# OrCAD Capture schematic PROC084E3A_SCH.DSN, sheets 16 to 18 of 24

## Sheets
16 12. PRG1 GB_ETHERNET RGMII 2: size C; title: PRG1 GB_ETHERNET RGMII 2
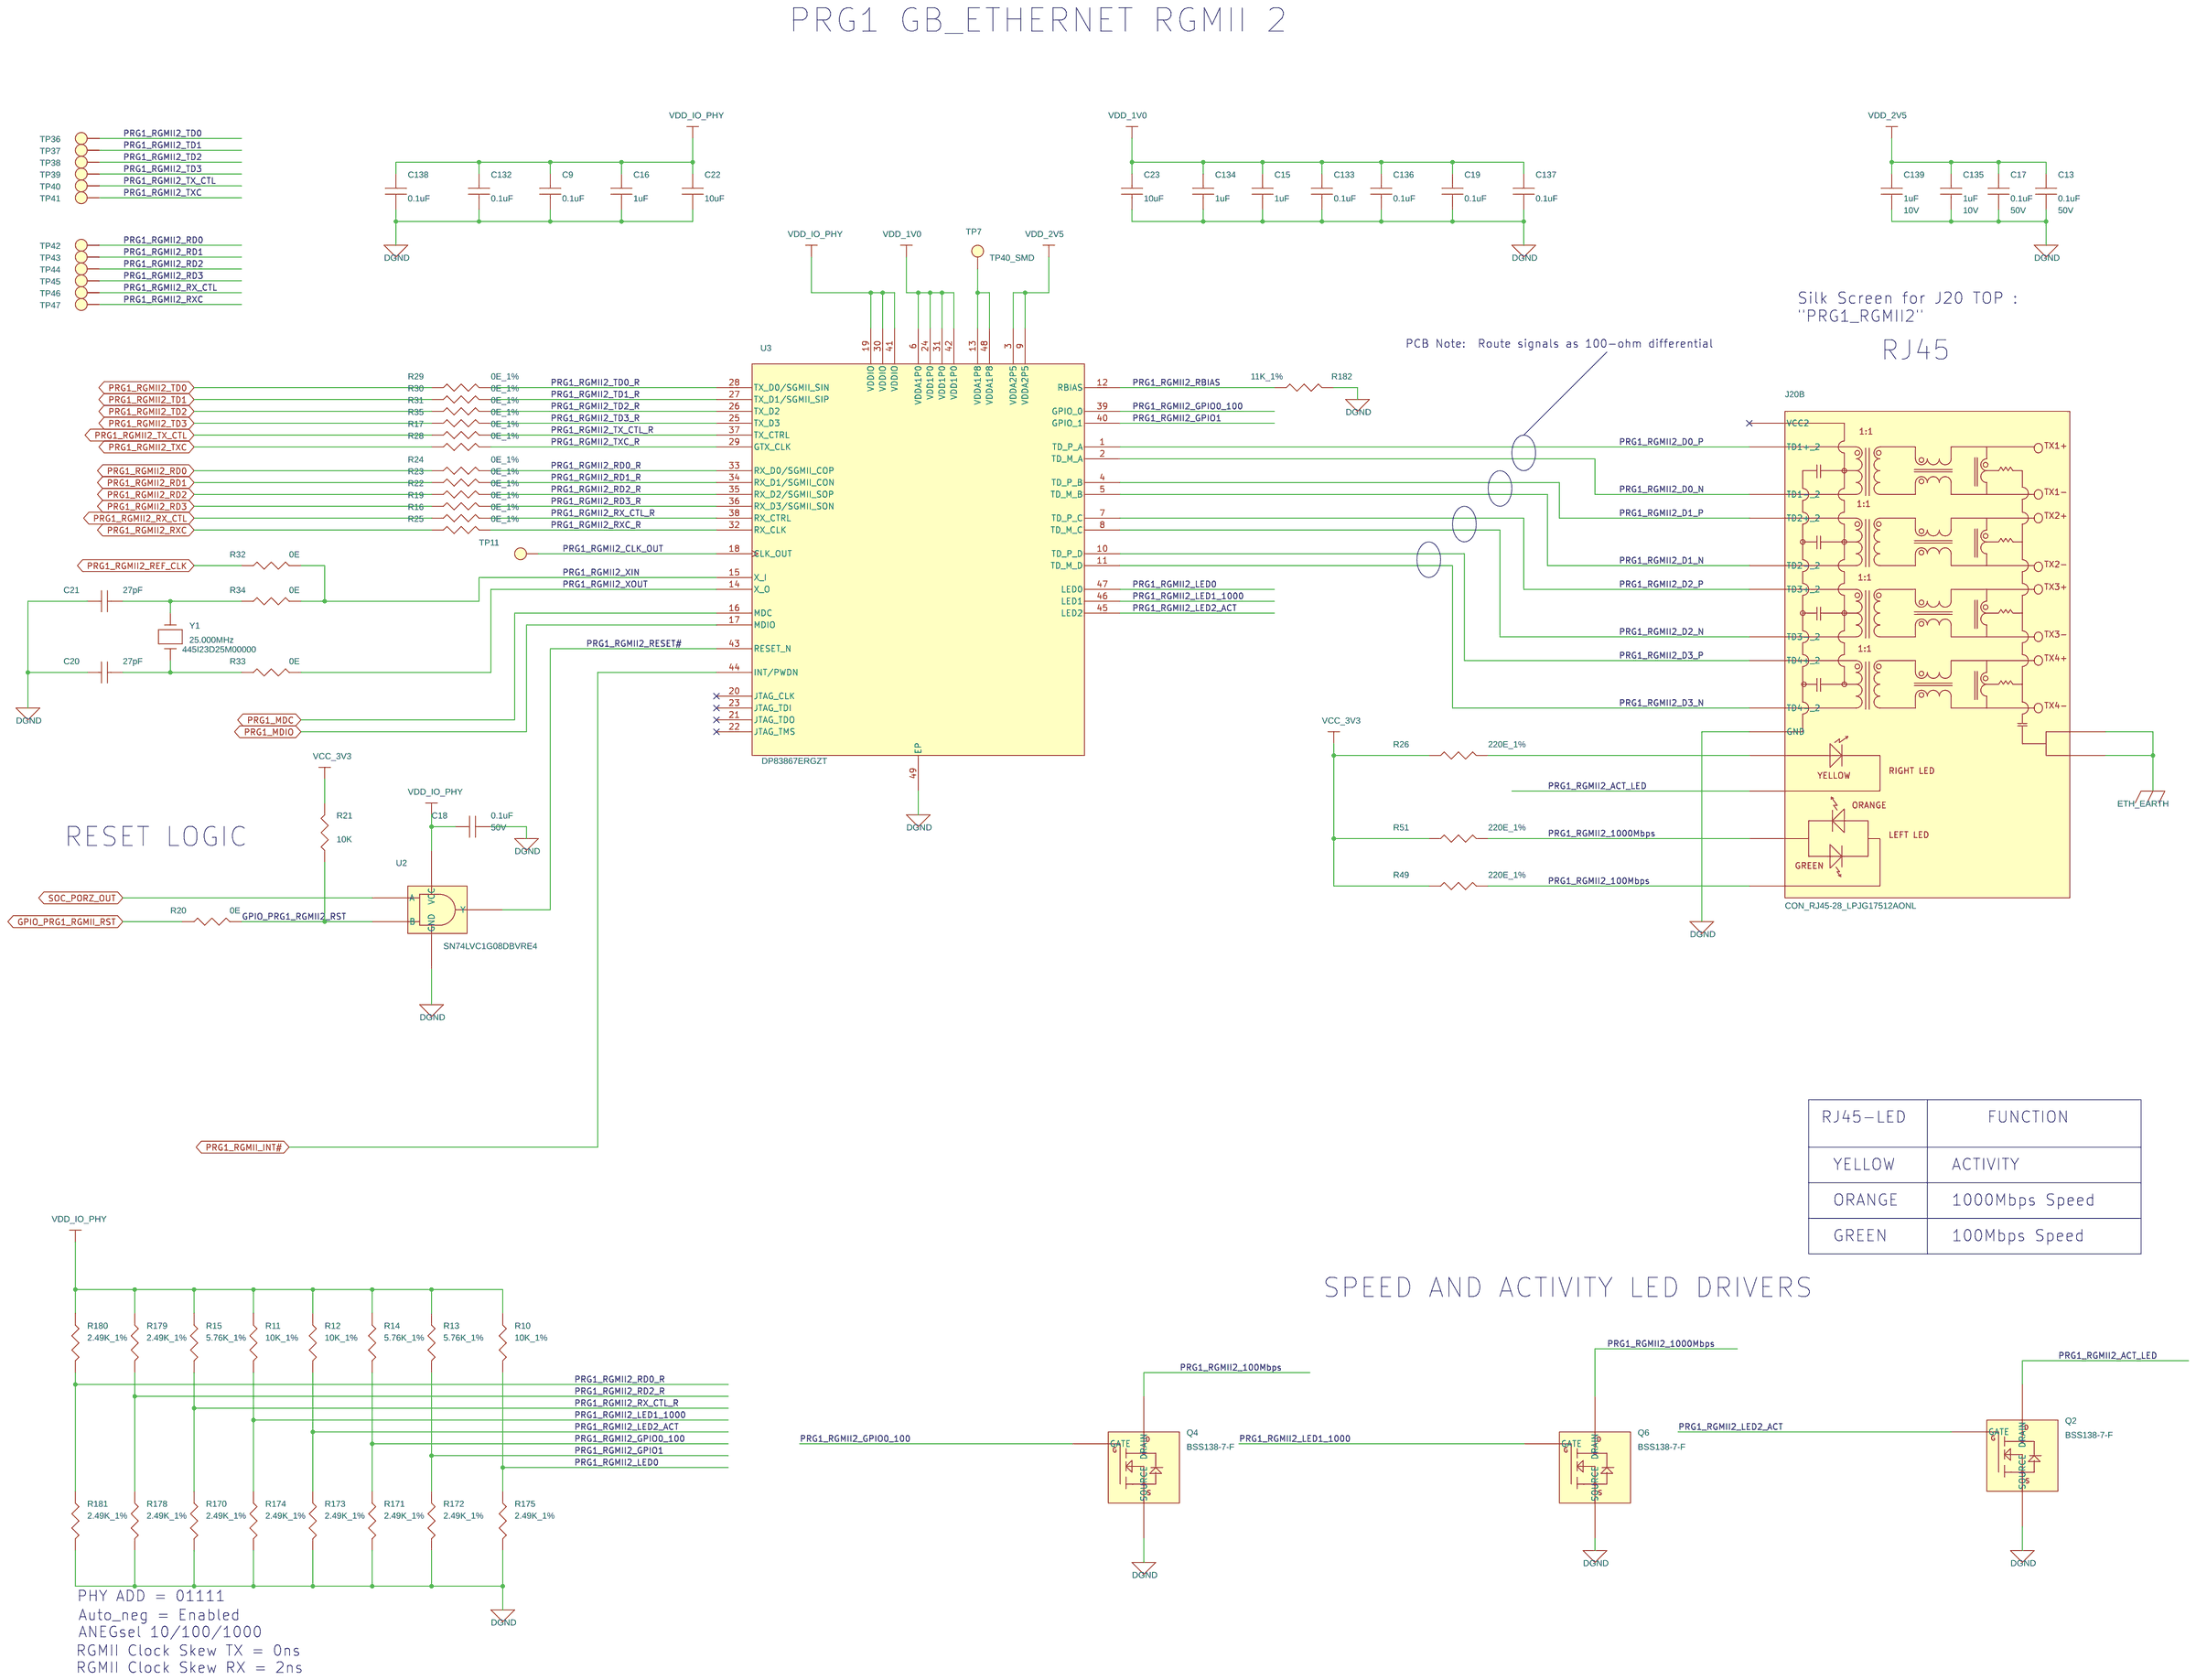
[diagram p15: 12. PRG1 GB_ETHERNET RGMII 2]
17 13. CAN TRANSCEIVERS - 01: size C; title: CAN TRANSCEIVERS - 01
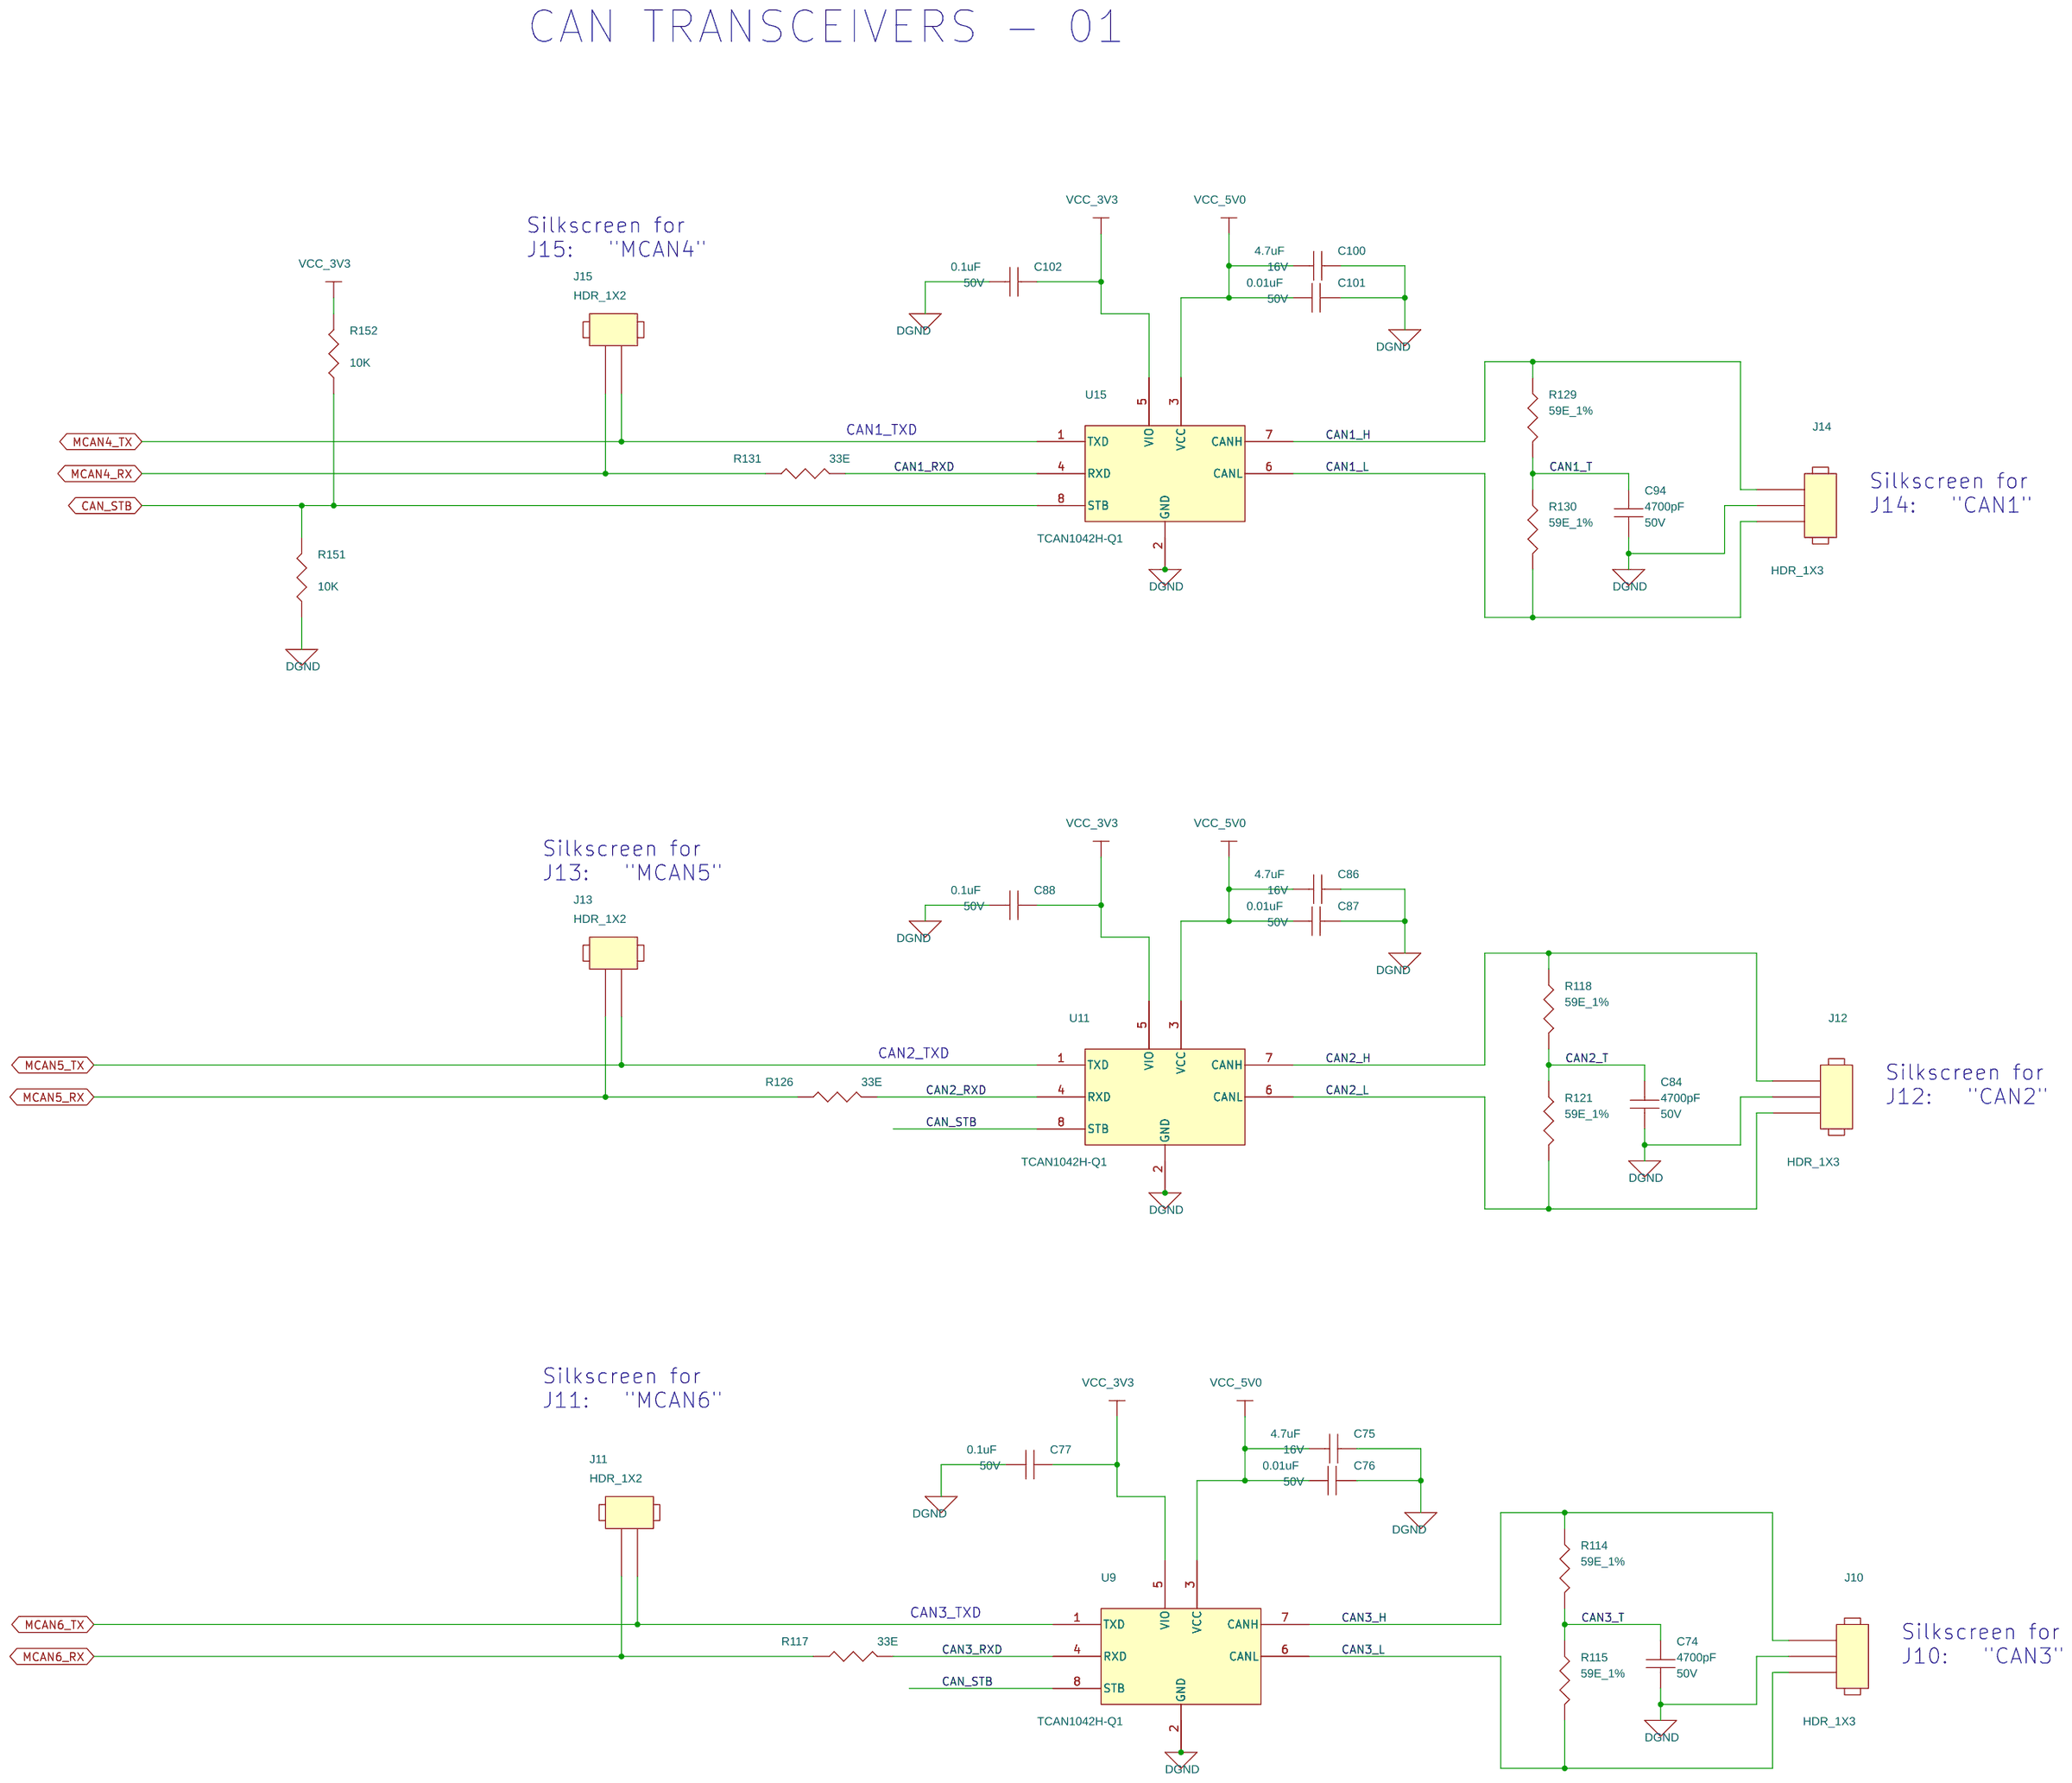
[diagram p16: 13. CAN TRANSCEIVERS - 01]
18 14. CAN TRANSCEIVERS - 02: size C; title: CAN TRANSCEIVERS - 02
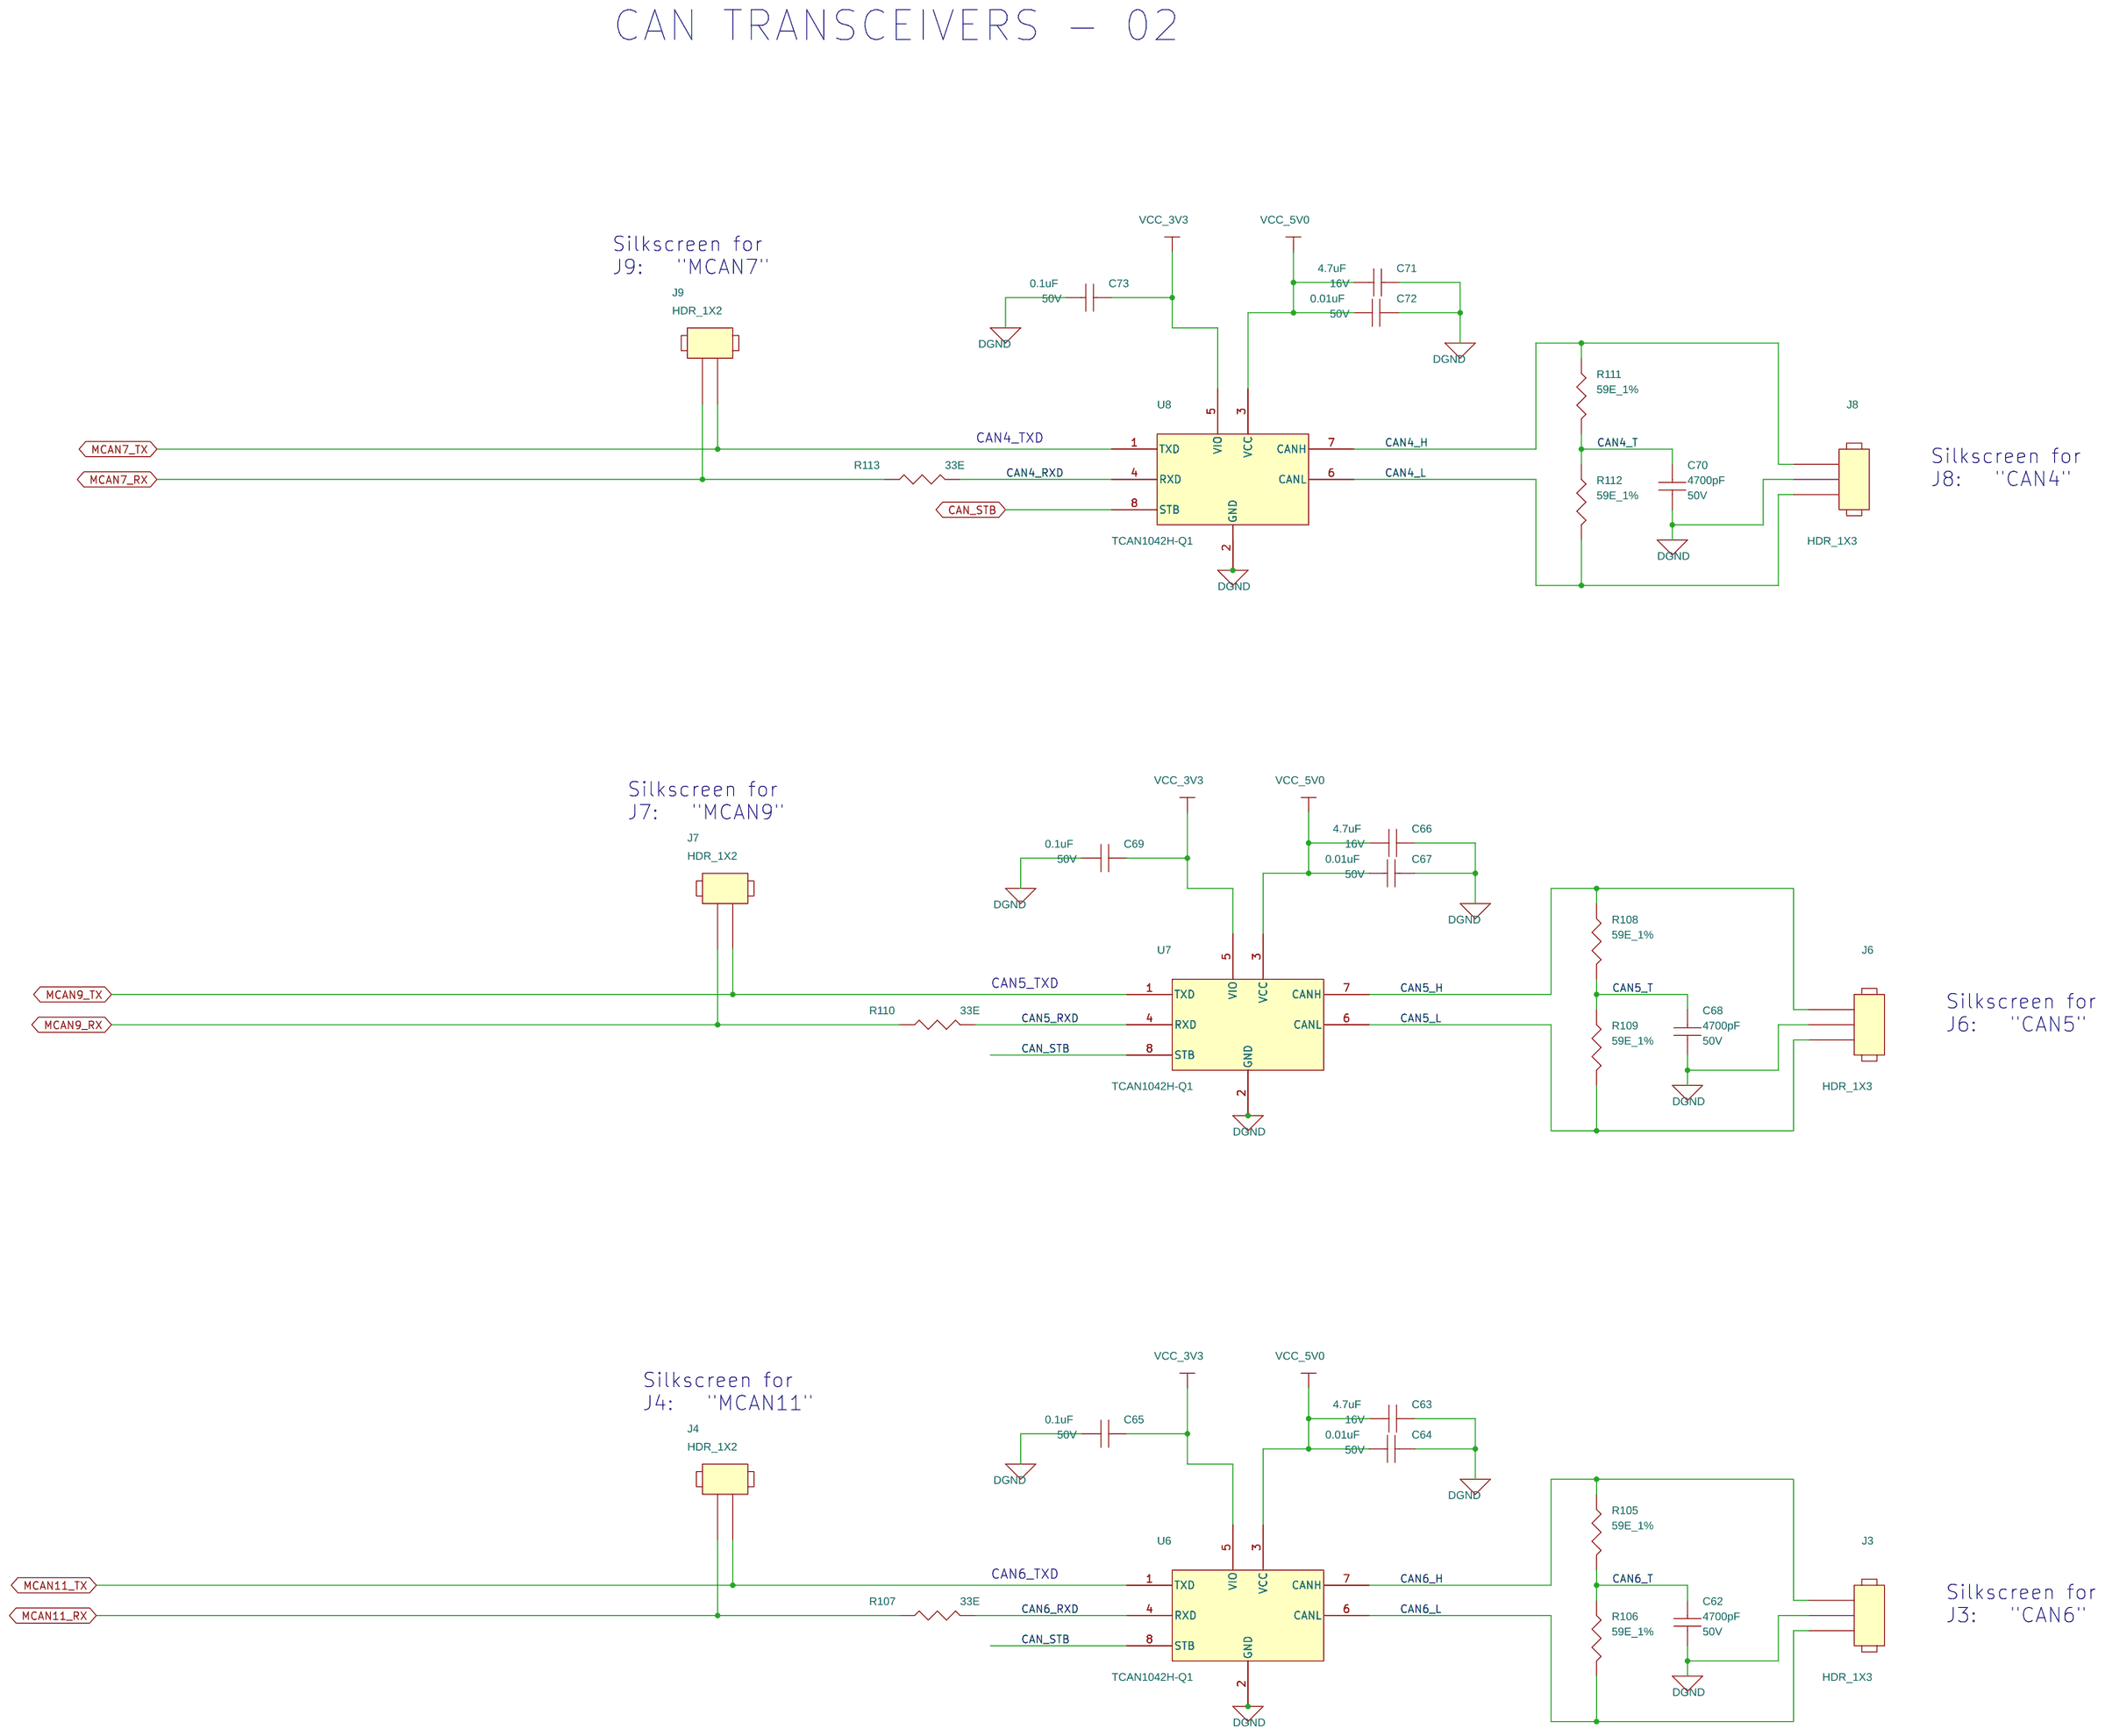
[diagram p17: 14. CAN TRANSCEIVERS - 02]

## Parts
sheet 12. PRG1 GB_ETHERNET RGMII 2
C9  0.1uF  [CAP0402_0-75]
C13  0.1uF  [CAP0402_0-75]
C15  1uF  [CAP0402_0-75]
C16  1uF  [CAP0402_0-75]
C17  0.1uF  [CAP0402_0-75]
C18  0.1uF  [CAP0402_0-75]
C19  0.1uF  [CAP0402_0-75]
C20  27pF  [CAP0402_0-75]
C21  27pF  [CAP0402_0-75]
C22  10uF  [CAP0805_1-5]
C23  10uF  [CAP0805_1-5]
C132  0.1uF  [CAP0402_0-75]
C133  0.1uF  [CAP0402_0-75]
C134  1uF  [CAP0402_0-75]
C135  1uF  [CAP0402_0-75]
C136  0.1uF  [CAP0402_0-75]
C137  0.1uF  [CAP0402_0-75]
C138  0.1uF  [CAP0402_0-75]
C139  1uF  [CAP0402_0-75]
J20  CON_RJ45-28_LPJG17512AONL  [CON_RJ45-28_LPJG17512_S_R_T_25-3]  (sections A,B)
Q2  BSS138-7-F  [SOT23-123_1-1]
Q4  BSS138-7-F  [SOT23-123_1-1]
Q6  BSS138-7-F  [SOT23-123_1-1]
R10  10K_1%  [RES0402_0-5]
R11  10K_1%  [RES0402_0-5]
R12  10K_1%  [RES0402_0-5]
R13  5.76K_1%  [RES0402_0-5]
R14  5.76K_1%  [RES0402_0-5]
R15  5.76K_1%  [RES0402_0-5]
R16  0E_1%  [RES0402_0-5]
R17  0E_1%  [RES0402_0-5]
R19  0E_1%  [RES0402_0-5]
R20  0E  [RES0402_0-5]
R21  10K  [RES0402_0-5]
R22  0E_1%  [RES0402_0-5]
R23  0E_1%  [RES0402_0-5]
R24  0E_1%  [RES0402_0-5]
R25  0E_1%  [RES0402_0-5]
R26  220E_1%  [RES0402_0-5]
R28  0E_1%  [RES0402_0-5]
R29  0E_1%  [RES0402_0-5]
R30  0E_1%  [RES0402_0-5]
R31  0E_1%  [RES0402_0-5]
R32  0E  [RES0402_0-5]
R33  0E  [RES0402_0-5]
R34  0E  [RES0402_0-5]
R35  0E_1%  [RES0402_0-5]
R49  220E_1%  [RES0402_0-5]
R51  220E_1%  [RES0402_0-5]
R170  2.49K_1%  [RES0402_0-5]
R171  2.49K_1%  [RES0402_0-5]
R172  2.49K_1%  [RES0402_0-5]
R173  2.49K_1%  [RES0402_0-5]
R174  2.49K_1%  [RES0402_0-5]
R175  2.49K_1%  [RES0402_0-5]
R178  2.49K_1%  [RES0402_0-5]
R179  2.49K_1%  [RES0402_0-5]
R180  2.49K_1%  [RES0402_0-5]
R181  2.49K_1%  [RES0402_0-5]
R182  11K_1%  [RES0402_0-5]
TP7  TP40_SMD  [TP40_SMD]
TP11  TP40_SMD  [TP40_SMD]
TP36  TP20_SMD  [TP20_SMD]
TP37  TP20_SMD  [TP20_SMD]
TP38  TP20_SMD  [TP20_SMD]
TP39  TP20_SMD  [TP20_SMD]
TP40  TP20_SMD  [TP20_SMD]
TP41  TP20_SMD  [TP20_SMD]
TP42  TP20_SMD  [TP20_SMD]
TP43  TP20_SMD  [TP20_SMD]
TP44  TP20_SMD  [TP20_SMD]
TP45  TP20_SMD  [TP20_SMD]
TP46  TP20_SMD  [TP20_SMD]
TP47  TP20_SMD  [TP20_SMD]
U2  SN74LVC1G08DBVRE4  [SOT23-5]
U3  DP83867ERGZT  [VQFN48_19-68_285X285]
Y1  25.000MHz  [XTAL_ABM3_205X130_SMD_1-4]
sheet 13. CAN TRANSCEIVERS - 01
C74  4700pF  [CAP0402_0-75]
C75  4.7uF  [CAP0603_1]
C76  0.01uF  [CAP0402_0-75]
C77  0.1uF  [CAP0402_0-75]
C84  4700pF  [CAP0402_0-75]
C86  4.7uF  [CAP0603_1]
C87  0.01uF  [CAP0402_0-75]
C88  0.1uF  [CAP0402_0-75]
C94  4700pF  [CAP0402_0-75]
C100  4.7uF  [CAP0603_1]
C101  0.01uF  [CAP0402_0-75]
C102  0.1uF  [CAP0402_0-75]
J10  HDR_1X3  [HDR_3X1_100_S_T]
J11  HDR_1X2  [HDR_1X2_68002-202_S_T_8-6]
J12  HDR_1X3  [HDR_3X1_100_S_T]
J13  HDR_1X2  [HDR_1X2_68002-202_S_T_8-6]
J14  HDR_1X3  [HDR_3X1_100_S_T]
J15  HDR_1X2  [HDR_1X2_68002-202_S_T_8-6]
R114  59E_1%  [RES0402_0-5]
R115  59E_1%  [RES0402_0-5]
R117  33E  [RES0402_0-5]
R118  59E_1%  [RES0402_0-5]
R121  59E_1%  [RES0402_0-5]
R126  33E  [RES0402_0-5]
R129  59E_1%  [RES0402_0-5]
R130  59E_1%  [RES0402_0-5]
R131  33E  [RES0402_0-5]
R151  10K  [RES0402_0-5]
R152  10K  [RES0402_0-5]
U9  TCAN1042H-Q1  [SOIC8_1-8]
U11  TCAN1042H-Q1  [SOIC8_1-8]
U15  TCAN1042H-Q1  [SOIC8_1-8]
sheet 14. CAN TRANSCEIVERS - 02
C62  4700pF  [CAP0402_0-75]
C63  4.7uF  [CAP0603_1]
C64  0.01uF  [CAP0402_0-75]
C65  0.1uF  [CAP0402_0-75]
C66  4.7uF  [CAP0603_1]
C67  0.01uF  [CAP0402_0-75]
C68  4700pF  [CAP0402_0-75]
C69  0.1uF  [CAP0402_0-75]
C70  4700pF  [CAP0402_0-75]
C71  4.7uF  [CAP0603_1]
C72  0.01uF  [CAP0402_0-75]
C73  0.1uF  [CAP0402_0-75]
J3  HDR_1X3  [HDR_3X1_100_S_T]
J4  HDR_1X2  [HDR_1X2_68002-202_S_T_8-6]
J6  HDR_1X3  [HDR_3X1_100_S_T]
J7  HDR_1X2  [HDR_1X2_68002-202_S_T_8-6]
J8  HDR_1X3  [HDR_3X1_100_S_T]
J9  HDR_1X2  [HDR_1X2_68002-202_S_T_8-6]
R105  59E_1%  [RES0402_0-5]
R106  59E_1%  [RES0402_0-5]
R107  33E  [RES0402_0-5]
R108  59E_1%  [RES0402_0-5]
R109  59E_1%  [RES0402_0-5]
R110  33E  [RES0402_0-5]
R111  59E_1%  [RES0402_0-5]
R112  59E_1%  [RES0402_0-5]
R113  33E  [RES0402_0-5]
U6  TCAN1042H-Q1  [SOIC8_1-8]
U7  TCAN1042H-Q1  [SOIC8_1-8]
U8  TCAN1042H-Q1  [SOIC8_1-8]

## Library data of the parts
C9 C13 C17-C19 C65 C69 C73 C77 C88 C102 C132 C133 C136-C138 = CAP: CAP CERAMIC 0.1uF 50V 10% X7R 0402; Chkd/date: VASANTHA/281216; Crtd /date: CHAITHANYA/051011; Custom_Duty: 15%; Customs_HS_Code: 85322990; Distributor_name: DIGIKEY; Distributor_part_number: 445-173610-1-ND; Footprint Path: Y:\MIS_DATABASE\Library\ALTIUM_TOOL\PCB_FOOTPRINTS\Altium_Footprint_Lib.PcbLib; Height: 0.60MM; Library Path: Y:\MIS_DATABASE\Library\ALTIUM_TOOL\SCHEMATICS_PARTS\MS_DISCRETE_Library.schlib; Mfr_name: TDK CORPORATION; Mfr_part_number: C1005X7R1H104K050BE; Mistral Part No: 120011100014-R; Package: 0402; Part_type: CAPACITORS\CERAMIC; Project: VP-4000-BASE-BOARD; RoHS: RoHS; Temperature: -55°C+125°C; Tolerance: 10%; Voltage: 50V; Wattage: NA; Weight: 0.65mg; Datasheet: Y:\MIS_DATABASE\DATASHEETS\CAPACITORS\TDK_C-SER_FEB19.PDF
C15 C16 C134 C135 C139 = CAP: CAP CERAMIC 1uF 10V 10% X5R 0402; Chkd/date: MANIRAJA/020718; Crtd /date: SARANYA/060514; Custom_Duty: 15%; Customs_HS_Code: 85322990; Distributor_name: DIGIKEY; Distributor_part_number: 478-4596-1-ND; Footprint Path: Y:\MIS_DATABASE\Library\ALTIUM_TOOL\PCB_FOOTPRINTS\Altium_Footprint_Lib.PcbLib; Height: 0.56MM; Library Path: Y:\MIS_DATABASE\Library\ALTIUM_TOOL\SCHEMATICS_PARTS\MS_DISCRETE_Library.schlib; Mfr_name: AVX CORPORATION; Mfr_part_number: 0402ZD105KAT2A; Mistral Part No: 120014050010-R; Package: 0402; Part_type: CAPACITORS\CERAMIC; Project: AEGIS GP BETA2; RoHS: RoHS; Temperature: -55°C+85°C; Tolerance: 10%; Voltage: 10V; Wattage: NA; Weight: 0.65mg; Datasheet: Y:\MIS_DATABASE\DATASHEETS\CAPACITORS\AVX_MLC.PDF
C20 C21 = CAP: CAP CERAMIC 27pF 50V 5% C0G(NP0) 0402; Chkd/date: MAZHAR/241208; Crtd /date: GEETHA/090606; Custom_Duty: 15%; Customs_HS_Code: 85322990; Distributor_name: DIGIKEY; Distributor_part_number: 311-1019-1-ND; Footprint Path: Y:\MIS_DATABASE\Library\ALTIUM_TOOL\PCB_FOOTPRINTS\Altium_Footprint_Lib.PcbLib; Height: 0.55MM; Library Path: Y:\MIS_DATABASE\Library\ALTIUM_TOOL\SCHEMATICS_PARTS\MS_DISCRETE_Library.schlib; Mfr_name: YAGEO AMERICA; Mfr_part_number: CC0402JRNPO9BN270; Mistral Part No: 120014100024-R; Package: 0402; Part_type: CAPACITORS\CERAMIC; Project: PNAV; RoHS: RoHS; Temperature: -55°C+125°C; Tolerance: 5%; Voltage: 50V; Wattage: NA; Weight: 0.65mg; Datasheet: Y:\MIS_DATABASE\DATASHEETS\CAPACITORS\YACC-NPO.PDF
C22 C23 = CAP: CAP CERAMIC 10uF 16V 10% X5R 0805; Chkd/date: SHREESHAIL/220506; Crtd /date: MAZHAR/150506; Custom_Duty: 15%; Customs_HS_Code: 85322990; Distributor_name: DIGIKEY; Distributor_part_number: 490-3886-1-ND; Footprint Path: Y:\MIS_DATABASE\Library\ALTIUM_TOOL\PCB_FOOTPRINTS\Altium_Footprint_Lib.PcbLib; Height: 1.35MM; Library Path: Y:\MIS_DATABASE\Library\ALTIUM_TOOL\SCHEMATICS_PARTS\MS_DISCRETE_Library.schlib; Mfr_name: MURATA; Mfr_part_number: GRM21BR61C106KE15L; Mistral Part No: 120009030205-R; Package: 0805; Part_type: CAPACITORS\CERAMIC; Project: VOCERA; RoHS: RoHS; Temperature: -55°C+85°C; Tolerance: 10%; Voltage: 16V; Wattage: NA; Weight: 9.5mg; Datasheet: Y:\MIS_DATABASE\DATASHEETS\CAPACITORS\MURATA-GXX-SER_NOV17.PDF
J20 = CON_RJ45-28_LPJG17512AONL: CON JACK RJ45 28POS REGISTERED FEMALE RA TH; Chkd/date: MANIRAJA/010817; Crtd /date: MANIRAJA/010817; Custom_Duty: 24%; Customs_HS_Code: 85369090; Distributor_name: NA; Distributor_part_number: NA; Height: 25.30MM; Mfr_name: LINK-PP; Mfr_part_number: LPJG17512AONL; Mistral Part No: 150017080001-R; Package: THRU-HOLE; Part_type: CONNECTOR\JACK; Project: TI_SVB_DUT; RoHS: RoHS; Temperature: 0°C+70°C; Tolerance: NA; Voltage: NA; Wattage: NA; Weight: NA; Datasheet: Y:\MIS_DATABASE\DATASHEETS\CONNECTORS\LPJG17512AONL.PDF
Q2 Q4 Q6 = MOSFET_2N7002_SOT23: IC MOSFET N-CHANNEL 50V 200mA SOT23-123; Chkd/date: MANIRAJA/190618; Crtd /date: USMAN/240709; Custom_Duty: 15%; Customs_HS_Code: 85423100; Distributor_name: DIGIKEY; Distributor_part_number: BSS138-FDICT-ND; Footprint Path: Y:\MIS_DATABASE\Library\ALTIUM_TOOL\PCB_FOOTPRINTS\Altium_Footprint_Lib.PcbLib; Height: 1.10MM; Library Path: Y:\MIS_DATABASE\Library\ALTIUM_TOOL\SCHEMATICS_PARTS\MS_MOSFET_Library.schlib; Mfr_name: DIODES INC; Mistral Part No: 142009070019-R; Package: SOT23-123; Part_type: ICS\POWER\MOSFET; Project: KHAN_MAIN; RoHS: RoHS; Temperature: -55°C+150°C; Tolerance: NA; Voltage: 50V; Wattage: 300mW; Weight: 8mg; Datasheet: Y:\MIS_DATABASE\DATASHEETS\DISCRETES\TRANSISTORS_FETS\BSS138.PDF
R10 R12 = RESISTOR: RES 10K 1/16W 1% 0402; Assembly_Instruction: DNI; Chkd/date: VASANTHA/201216; Crtd /date: GEETHA/290506; Custom_Duty: 15%; Customs_HS_Code: 85332119; Distributor_name: DIGIKEY; Distributor_part_number: 311-10.0KLRTR-ND; Footprint Path: Y:\MIS_DATABASE\Library\ALTIUM_TOOL\PCB_FOOTPRINTS\Altium_Footprint_Lib.PcbLib; Height: 0.40MM; Library Path: Y:\MIS_DATABASE\Library\ALTIUM_TOOL\SCHEMATICS_PARTS\MS_DISCRETE_Library.schlib; Mfr_name: YAGEO AMERICA; Mfr_part_number: RC0402FR-0710KL; Mistral Part No: 110015090015-R; Package: 0402; Part_type: RESISTORS\FIXED; Project: VOCERA; RoHS: RoHS; Temperature: -55°C+155°C; Tolerance: 1%; Voltage: NA; Wattage: 1/16W; Weight: 0.65mg; Datasheet: Y:\MIS_DATABASE\DATASHEETS\RESISTORS\RCXXXXL-SER_MAR18.PDF
R11 = RESISTOR: RES 10K 1/16W 1% 0402; Chkd/date: VASANTHA/201216; Crtd /date: GEETHA/290506; Custom_Duty: 15%; Customs_HS_Code: 85332119; Distributor_name: DIGIKEY; Distributor_part_number: 311-10.0KLRTR-ND; Footprint Path: Y:\MIS_DATABASE\Library\ALTIUM_TOOL\PCB_FOOTPRINTS\Altium_Footprint_Lib.PcbLib; Height: 0.40MM; Library Path: Y:\MIS_DATABASE\Library\ALTIUM_TOOL\SCHEMATICS_PARTS\MS_DISCRETE_Library.schlib; Mfr_name: YAGEO AMERICA; Mfr_part_number: RC0402FR-0710KL; Mistral Part No: 110015090015-R; Package: 0402; Part_type: RESISTORS\FIXED; Project: VOCERA; RoHS: RoHS; Temperature: -55°C+155°C; Tolerance: 1%; Voltage: NA; Wattage: 1/16W; Weight: 0.65mg; Datasheet: Y:\MIS_DATABASE\DATASHEETS\RESISTORS\RCXXXXL-SER_MAR18.PDF
R13 R14 = RESISTOR: RES 5.76K 1/10W 1% 0402; Assembly_Instruction: DNI; Chkd/date: MAZHAR/150709; Crtd /date: USMAN/220808; Custom_Duty: 15%; Customs_HS_Code: 85332119; Distributor_name: DIGIKEY; Distributor_part_number: P5.76KLCT-ND; Footprint Path: Y:\MIS_DATABASE\Library\ALTIUM_TOOL\PCB_FOOTPRINTS\Altium_Footprint_Lib.PcbLib; Height: 0.40MM; Library Path: Y:\MIS_DATABASE\Library\ALTIUM_TOOL\SCHEMATICS_PARTS\MS_DISCRETE_Library.schlib; Mfr_name: PANASONIC-ECG; Mfr_part_number: ERJ-2RKF5761X; Mistral Part No: 110009030945-R; Package: 0402; Part_type: RESISTORS\FIXED; Project: CPB; RoHS: RoHS; Temperature: -55°C+155°C; Tolerance: 1%; Voltage: NA; Wattage: 1/10W; Weight: 0.8mg; Datasheet: Y:\MIS_DATABASE\DATASHEETS\RESISTORS\PAN-ERJSER_NOV17.PDF
R15 = RESISTOR: RES 5.76K 1/10W 1% 0402; Chkd/date: MAZHAR/150709; Crtd /date: USMAN/220808; Custom_Duty: 15%; Customs_HS_Code: 85332119; Distributor_name: DIGIKEY; Distributor_part_number: P5.76KLCT-ND; Footprint Path: Y:\MIS_DATABASE\Library\ALTIUM_TOOL\PCB_FOOTPRINTS\Altium_Footprint_Lib.PcbLib; Height: 0.40MM; Library Path: Y:\MIS_DATABASE\Library\ALTIUM_TOOL\SCHEMATICS_PARTS\MS_DISCRETE_Library.schlib; Mfr_name: PANASONIC-ECG; Mfr_part_number: ERJ-2RKF5761X; Mistral Part No: 110009030945-R; Package: 0402; Part_type: RESISTORS\FIXED; Project: CPB; RoHS: RoHS; Temperature: -55°C+155°C; Tolerance: 1%; Voltage: NA; Wattage: 1/10W; Weight: 0.8mg; Datasheet: Y:\MIS_DATABASE\DATASHEETS\RESISTORS\PAN-ERJSER_NOV17.PDF
R16 R19 R22-R25 = RESISTOR: RES 0E 1/16W 1% 0402; Chkd/date: MAZHAR/220709; Crtd /date: USMAN/270109; Custom_Duty: 15%; Customs_HS_Code: 85332119; Distributor_name: DIGIKEY; Distributor_part_number: 311-0.0LRCT-ND; Footprint Path: Y:\MIS_DATABASE\Library\ALTIUM_TOOL\PCB_FOOTPRINTS\Altium_Footprint_Lib.PcbLib; Height: 0.40MM; Library Path: Y:\MIS_DATABASE\Library\ALTIUM_TOOL\SCHEMATICS_PARTS\MS_DISCRETE_Library.schlib; Mfr_name: YAGEO AMERICA; Mfr_part_number: RC0402FR-070RL; Mistral Part No: 110009030085-R; Package: 0402; Part_type: RESISTORS\FIXED; Project: OMAP_EVM; RoHS: RoHS; SIGNAL_MODEL: RESISTOR_RES0402_22E_1%_22E_1%; Temperature: -55°C+155°C; Tolerance: 1%; Voltage: NA; Wattage: 1/16W; Weight: 0.65mg; Datasheet: Y:\MIS_DATABASE\DATASHEETS\RESISTORS\RCXXXXL-SER_MAR18.PDF
R17 R28-R31 R35 = RESISTOR: RES 0E 1/16W 1% 0402; Chkd/date: MAZHAR/220709; Crtd /date: USMAN/270109; Custom_Duty: 15%; Customs_HS_Code: 85332119; Distributor_name: DIGIKEY; Distributor_part_number: 311-0.0LRCT-ND; Footprint Path: Y:\MIS_DATABASE\Library\ALTIUM_TOOL\PCB_FOOTPRINTS\Altium_Footprint_Lib.PcbLib; Height: 0.40MM; Library Path: Y:\MIS_DATABASE\Library\ALTIUM_TOOL\SCHEMATICS_PARTS\MS_DISCRETE_Library.schlib; Mfr_name: YAGEO AMERICA; Mfr_part_number: RC0402FR-070RL; Mistral Part No: 110009030085-R; Package: 0402; Part_type: RESISTORS\FIXED; Project: OMAP_EVM; RoHS: RoHS; SIGNAL_MODEL: INS23888567; Temperature: -55°C+155°C; Tolerance: 1%; Voltage: NA; Wattage: 1/16W; Weight: 0.65mg; Datasheet: Y:\MIS_DATABASE\DATASHEETS\RESISTORS\RCXXXXL-SER_MAR18.PDF
R20 R33 R34 = RESISTOR: RES 0E 1/10W JUMPER 0402; Chkd/date: MANIRAJA/290318; Crtd /date: ALVY/270318; Custom_Duty: 15%; Customs_HS_Code: 85332119; Distributor_name: DIGIKEY; Distributor_part_number: MCS0402-0.0-ZZCT-ND; Footprint Path: Y:\MIS_DATABASE\Library\ALTIUM_TOOL\PCB_FOOTPRINTS\Altium_Footprint_Lib.PcbLib; Height: 0.37MM; Library Path: Y:\MIS_DATABASE\Library\ALTIUM_TOOL\SCHEMATICS_PARTS\MS_DISCRETE_Library.schlib; Mfr_name: VISHAY; Mfr_part_number: MCS04020Z0000ZE000; Mistral Part No: 110018030052-R; Package: 0402; Part_type: RESISTORS\FIXED; Project: DRDL_ITS2-SC; RoHS: RoHS; SIGNAL_MODEL: INS23888567; Temperature: -55°C+155°C; Tolerance: NA; Voltage: NA; Wattage: 1/10W; Weight: 0.65mg; Datasheet: Y:\MIS_DATABASE\DATASHEETS\RESISTORS\MCTXXXXC-SER.PDF
R21 R151 = RESISTOR: RES 10K 1/16W 5% 0402; Chkd/date: VASANTHA/061216; Crtd /date: MAZHAR/230805; Custom_Duty: 15%; Customs_HS_Code: 85332119; Distributor_name: DIGIKEY; Distributor_part_number: 311-10KJRCT-ND; Footprint Path: Y:\MIS_DATABASE\Library\ALTIUM_TOOL\PCB_FOOTPRINTS\Altium_Footprint_Lib.PcbLib; Height: 0.40MM; Library Path: Y:\MIS_DATABASE\Library\ALTIUM_TOOL\SCHEMATICS_PARTS\MS_DISCRETE_Library.schlib; Mfr_name: YAGEO AMERICA; Mfr_part_number: RC0402JR-0710KL; Mistral Part No: 110011060021-R; Package: 0402; Part_type: RESISTORS\FIXED; Project: HSE; RoHS: RoHS; Temperature: -55°C+155°C; Tolerance: 5%; Voltage: NA; Wattage: 1/16W; Weight: 0.65mg; Datasheet: Y:\MIS_DATABASE\DATASHEETS\RESISTORS\RCXXXXL-SER_MAR18.PDF
R26 R49 R51 = RESISTOR: RES 220E 1/10W 1% 0402; Chkd/date: MANIRAJA/130617; Crtd /date: BAVISH/260711; Custom_Duty: 15%; Customs_HS_Code: 85332119; Distributor_name: DIGIKEY; Distributor_part_number: P220LCT-ND; Footprint Path: Y:\MIS_DATABASE\Library\ALTIUM_TOOL\PCB_FOOTPRINTS\Altium_Footprint_Lib.PcbLib; Height: 0.40MM; Library Path: Y:\MIS_DATABASE\Library\ALTIUM_TOOL\SCHEMATICS_PARTS\MS_DISCRETE_Library.schlib; Mfr_name: PANASONIC-ECG; Mfr_part_number: ERJ-2RKF2200X; Mistral Part No: 110011070017-R; Package: 0402; Part_type: RESISTORS\FIXED; Project: LSM; RoHS: RoHS; Temperature: -55°C+155°C; Tolerance: 1%; Voltage: NA; Wattage: 1/10W; Weight: 0.8mg; Datasheet: Y:\MIS_DATABASE\DATASHEETS\RESISTORS\PAN-ERJSER_NOV17.PDF
R32 = RESISTOR: RES 0E 1/10W JUMPER 0402; Assembly_Instruction: DNI; Chkd/date: MANIRAJA/290318; Crtd /date: ALVY/270318; Custom_Duty: 15%; Customs_HS_Code: 85332119; Distributor_name: DIGIKEY; Distributor_part_number: MCS0402-0.0-ZZCT-ND; Footprint Path: Y:\MIS_DATABASE\Library\ALTIUM_TOOL\PCB_FOOTPRINTS\Altium_Footprint_Lib.PcbLib; Height: 0.37MM; Library Path: Y:\MIS_DATABASE\Library\ALTIUM_TOOL\SCHEMATICS_PARTS\MS_DISCRETE_Library.schlib; Mfr_name: VISHAY; Mfr_part_number: MCS04020Z0000ZE000; Mistral Part No: 110018030052-R; Package: 0402; Part_type: RESISTORS\FIXED; Project: DRDL_ITS2-SC; RoHS: RoHS; SIGNAL_MODEL: INS23888567; Temperature: -55°C+155°C; Tolerance: NA; Voltage: NA; Wattage: 1/10W; Weight: 0.65mg; Datasheet: Y:\MIS_DATABASE\DATASHEETS\RESISTORS\MCTXXXXC-SER.PDF
R170 R174 R179 R180 = RESISTOR: RES 2.49K 1/16W 1% 0402; Chkd/date: VASANTHA/270516; Crtd /date: VASANTHA/270516; Custom_Duty: 15%; Customs_HS_Code: 85332119; Distributor_name: DIGIKEY; Distributor_part_number: 311-2.49KLRCT-ND; Footprint Path: Y:\MIS_DATABASE\Library\ALTIUM_TOOL\PCB_FOOTPRINTS\Altium_Footprint_Lib.PcbLib; Height: 0.40MM; Library Path: Y:\MIS_DATABASE\Library\ALTIUM_TOOL\SCHEMATICS_PARTS\MS_DISCRETE_Library.schlib; Mfr_name: YAGEO AMERICA; Mfr_part_number: RC0402FR-072K49L; Mistral Part No: 110016050020-R; Package: 0402; Part_type: RESISTORS\FIXED; Project: TMDXCSKCC; RoHS: RoHS; Temperature: -55°C+155°C; Tolerance: 1%; Voltage: NA; Wattage: 1/16W; Weight: 0.65mg; Datasheet: Y:\MIS_DATABASE\DATASHEETS\RESISTORS\RCXXXXL-SER_MAR18.PDF
R171-R173 R175 R178 R181 = RESISTOR: RES 2.49K 1/16W 1% 0402; Assembly_Instruction: DNI; Chkd/date: VASANTHA/270516; Crtd /date: VASANTHA/270516; Custom_Duty: 15%; Customs_HS_Code: 85332119; Distributor_name: DIGIKEY; Distributor_part_number: 311-2.49KLRCT-ND; Footprint Path: Y:\MIS_DATABASE\Library\ALTIUM_TOOL\PCB_FOOTPRINTS\Altium_Footprint_Lib.PcbLib; Height: 0.40MM; Library Path: Y:\MIS_DATABASE\Library\ALTIUM_TOOL\SCHEMATICS_PARTS\MS_DISCRETE_Library.schlib; Mfr_name: YAGEO AMERICA; Mfr_part_number: RC0402FR-072K49L; Mistral Part No: 110016050020-R; Package: 0402; Part_type: RESISTORS\FIXED; Project: TMDXCSKCC; RoHS: RoHS; Temperature: -55°C+155°C; Tolerance: 1%; Voltage: NA; Wattage: 1/16W; Weight: 0.65mg; Datasheet: Y:\MIS_DATABASE\DATASHEETS\RESISTORS\RCXXXXL-SER_MAR18.PDF
R182 = RESISTOR: RES 11K 1/16W 1% 0402; Chkd/date: VASANTHA/251115; Crtd /date: VASANTHA/251115; Custom_Duty: 15%; Customs_HS_Code: 85332119; Distributor_name: DIGIKEY; Distributor_part_number: 311-11.0KLRCT-ND; Footprint Path: Y:\MIS_DATABASE\Library\ALTIUM_TOOL\PCB_FOOTPRINTS\Altium_Footprint_Lib.PcbLib; Height: 0.40MM; Library Path: Y:\MIS_DATABASE\Library\ALTIUM_TOOL\SCHEMATICS_PARTS\MS_DISCRETE_Library.schlib; Mfr_name: YAGEO AMERICA; Mfr_part_number: RC0402FR-0711KL; Mistral Part No: 110015110012-R; Package: 0402; Part_type: RESISTORS\FIXED; Project: TI_VLAN_SWITCH; RoHS: RoHS; Temperature: -55°C+155°C; Tolerance: 1%; Voltage: NA; Wattage: 1/16W; Weight: 0.65mg; Datasheet: Y:\MIS_DATABASE\DATASHEETS\RESISTORS\RCXXXXL-SER_MAR18.PDF
TP7 TP11 = TESTPOINT: TESTPOINT CIR 40 SMD; Chkd/date: MAZHAR/190505; Crtd /date: MAZHAR/190505; Distributor_name: NA; Distributor_part_number: NA; Footprint Path: Y:\MIS_DATABASE\Library\ALTIUM_TOOL\PCB_FOOTPRINTS\Altium_Footprint_Lib.PcbLib; Height: NA; Library Path: Y:\MIS_DATABASE\Library\ALTIUM_TOOL\SCHEMATICS_PARTS\MS_DISCRETE_Library.schlib; MECHANICAL 3D STEP FILE: NA; Mfr_name: LOCAL; Mistral Part No: 130009030933; Package: SMD; Project: RAINIER-3; RoHS: NA; Temperature: NA; Tolerance: NA; Voltage: NA; Wattage: NA; Weight: NA; Datasheet: NA
TP36-TP47 = TESTPOINT: TESTPOINT CIR 20 SMD; Chkd/date: SHREESHAIL/171006; Crtd /date: MAZHAR/171006; Custom_Duty: NA; Customs_HS_Code: NA; Distributor_name: NA; Distributor_part_number: NA; Footprint Path: Y:\MIS_DATABASE\Library\ALTIUM_TOOL\PCB_FOOTPRINTS\Altium_Footprint_Lib.PcbLib; Height: NA; Library Path: Y:\MIS_DATABASE\Library\ALTIUM_TOOL\SCHEMATICS_PARTS\MS_DISCRETE_Library.schlib; MECHANICAL 3D STEP FILE: NA; Mfr_name: LOCAL; Mistral Part No: NA; Package: SMD; Project: BT MODULE_CSRBC04; RoHS: NA; Temperature: NA; Tolerance: NA; Voltage: NA; Wattage: NA; Weight: NA; Datasheet: NA
U2 = SN74LVC1G08DBVRE4_SOT23-5: IC SINGLE 2-INPUT POSITIVE AND GATE SOT23-5; Chkd/date: SUHAS/221010; Crtd /date: USMAN/151008; Custom_Duty: 15%; Customs_HS_Code: 85423100; Distributor_name: DIGIKEY; Distributor_part_number: SN74LVC1G08DBVRE4-ND; Height: 1.45MM; Mfr_name: TEXAS INSTRUMENTS; Mistral Part No: 141009060026-R; Part_type: ICS\DIGITAL\GATES; Project: KHAN_MAIN; RoHS: Sb/ Br FREE; Temperature: -40°C+85°C; Datasheet: Y:\MIS_DATABASE\DATASHEETS\ICS\DIGITAL\GATES\SN74LVC1G08.PDF
U3 = DP83867ERGZT_VQFN48: IC SMALL FORM FACTOR 10/100/1000 Mb/s ETHERNET PHY LAYER TRANSCEIVER VQFN48; Chkd/date: VASANTHA/251115; Crtd /date: VASANTHA/251115; Custom_Duty: 15%; Customs_HS_Code: 85423100; Distributor_name: DIGIKEY; Distributor_part_number: 296-43254-1-ND; Height: 1.00MM; Mfr_name: TEXAS INSTRUMENTS; Mistral Part No: 143015110004-R; Package: VQFN48; Part_type: ICS\TELECOM\TRANSCEIVER; Project: TI_VLAN_SWITCH; RoHS: RoHS; Temperature: -40°C+105°C; Tolerance: NA; Voltage: NA; Wattage: NA; Weight: NA; Datasheet: Y:\MIS_DATABASE\DATASHEETS\ICS\DIGITAL\BUSTRANSCEIVER\DP83867.PDF
Y1 = CRY: CRY 25.000MHz 18pF SMD; Chkd/date: VASANTHA/110316; Crtd /date: JEBRAN/090216; Custom_Duty: 24%; Customs_HS_Code: 85439000; Distributor_name: DIGIKEY; Distributor_part_number: CTX1175CT-ND; Footprint Path: Y:\MIS_DATABASE\Library\ALTIUM_TOOL\PCB_FOOTPRINTS\Altium_Footprint_Lib.PcbLib; Height: 1.35MM; Library Path: Y:\MIS_DATABASE\Library\ALTIUM_TOOL\SCHEMATICS_PARTS\MS_DISCRETE_Library.schlib; Mfr_name: CTS; Mfr_part_number: 445I23D25M00000; Mistral Part No: 130016020016-R; Package: SMD; Part_type: CRYSTAL; Project: PDI_MINIPCB; RoHS: RoHS; Temperature: -40°C+85°C; Tolerance: NA; Voltage: NA; Wattage: NA; Weight: 50mg; Datasheet: Y:\MIS_DATABASE\DATASHEETS\MISC\CRY_OSC\445.PDF
C62 C68 C70 C74 C84 C94 = CAP: CAP CERAMIC 4700pF 50V 5% X7R 0402; Chkd/date: MANIRAJA/070619; Crtd /date: MANIRAJA/070619; Custom_Duty: 15%; Customs_HS_Code: 85322990; Distributor_name: DIGIKEY; Distributor_part_number: 399-8968-1-ND; Footprint Path: Y:\MIS_DATABASE\Library\ALTIUM_TOOL\PCB_FOOTPRINTS\Altium_Footprint_Lib.PcbLib; Height: 0.55MM; Library Path: Y:\MIS_DATABASE\Library\ALTIUM_TOOL\SCHEMATICS_PARTS\MS_DISCRETE_Library.schlib; Mfr_name: KEMET; Mfr_part_number: C0402C472J5RACTU; Mistral Part No: 120013090022-R; Package: 0402; Part_type: CAPACITORS\CERAMIC; Project: J7ES_SOM_DUAL-LEO_PMIC; RoHS: RoHS; Temperature: -55°C+125°C; Tolerance: 5%; Voltage: 50V; Wattage: NA; Weight: 0.65mg; Datasheet: Y:\MIS_DATABASE\DATASHEETS\CAPACITORS\KEMET-C-X7R.PDF
C63 C66 C71 C75 C86 C100 = CAP: CAP CERAMIC 4.7uF 16V 10% X5R 0603; Chkd/date: VASANTHA/230714; Crtd /date: BAVISH/060511; Custom_Duty: 15%; Customs_HS_Code: 85322990; Distributor_name: DIGIKEY; Distributor_part_number: 587-2786-1-ND; Footprint Path: Y:\MIS_DATABASE\Library\ALTIUM_TOOL\PCB_FOOTPRINTS\Altium_Footprint_Lib.PcbLib; Height: 0.90MM; Library Path: Y:\MIS_DATABASE\Library\ALTIUM_TOOL\SCHEMATICS_PARTS\MS_DISCRETE_Library.schlib; Mfr_name: TAIYO YUDEN; Mfr_part_number: EMK107ABJ475KA-T; Mistral Part No: 120011050004-R; Package: 0603; Part_type: CAPACITORS\CERAMIC; Project: HMC; RoHS: RoHS; Temperature: -55°C+85°C; Tolerance: 10%; Voltage: 16V; Wattage: NA; Weight: 2mg; Datasheet: Y:\MIS_DATABASE\DATASHEETS\CAPACITORS\EMK107.PDF
C64 C67 C72 C76 C87 C101 = CAP: CAP CERAMIC 0.01uF 50V 10% X7R 0402; Chkd/date: SHREESHAIL/301105; Crtd /date: MAZHAR/040505; Custom_Duty: 15%; Customs_HS_Code: 85322990; Distributor_name: DIGIKEY; Distributor_part_number: 399-3066-1-ND; Footprint Path: Y:\MIS_DATABASE\Library\ALTIUM_TOOL\PCB_FOOTPRINTS\Altium_Footprint_Lib.PcbLib; Height: 0.55MM; Library Path: Y:\MIS_DATABASE\Library\ALTIUM_TOOL\SCHEMATICS_PARTS\MS_DISCRETE_Library.schlib; Mfr_name: KEMET; Mfr_part_number: C0402C103K5RACTU; Mistral Part No: 120009030025-R; Package: 0402; Part_type: CAPACITORS\CERAMIC; Project: G4_SVGA; RoHS: RoHS; Temperature: -55°C+125°C; Tolerance: 10%; Voltage: 50V; Wattage: NA; Weight: 0.65mg; Datasheet: Y:\MIS_DATABASE\DATASHEETS\CAPACITORS\KEMET-C-X7R.PDF
J3 J6 J8 J10 J12 J14 = HEADER_3X1: HDR 1X3 2.54MM PITCH ST TH; Chkd/date: VASANTHA/290616; Crtd /date: VASANTHA/290616; Custom_Duty: 15%; Customs_HS_Code: 85322990; Distributor_name: DIGIKEY; Distributor_part_number: 609-3471-ND; Height: 8.58MM; Mfr_name: FCI; Mfr_part_number: 68001-403HLF; Mistral Part No: 150016060025-R; Package: THRU-HOLE; Part_type: CONNECTOR\HEADERS; Project: IKEYP; RoHS: RoHS; Temperature: -40°C+105°C; Tolerance: NA; Voltage: NA; Wattage: NA; Weight: NA; Datasheet: Y:\MIS_DATABASE\DATASHEETS\CONNECTORS\68000.PDF
J4 J7 J9 J11 J13 J15 = HEADER_2X1: CON HDR 1X2 2.54MM PITCH ST TH; Chkd/date: MANIRAJA/190118; Crtd /date: ALVY/190118; Custom_Duty: 24%; Customs_HS_Code: 85369090; Distributor_name: DIGIKEY; Distributor_part_number: 68002-202HLF-ND; Height: 8.58MM; Mfr_name: AMPHENOL; Mfr_part_number: 68002-202HLF; Mistral Part No: 150018010012-R; Package: THRU HOLE; Part_type: CONNECTOR\HEADERS; Project: TI_SVB_MAXWELL_DUT; RoHS: RoHS; Temperature: NA; Tolerance: NA; Voltage: NA; Wattage: NA; Weight: NA; Datasheet: Y:\MIS_DATABASE\DATASHEETS\CONNECTORS\68002.PDF
R105 R106 R108 R109 R111 R112 R114 R115 R118 R121 R129 R130 = RESISTOR: RES 59E 1/10W 1% 0402; Chkd/date: MAZHAR/151208; Crtd /date: USMAN/031208; Custom_Duty: 15%; Customs_HS_Code: 85332119; Distributor_name: DIGIKEY; Distributor_part_number: P59.0LCT-ND; Footprint Path: Y:\MIS_DATABASE\Library\ALTIUM_TOOL\PCB_FOOTPRINTS\Altium_Footprint_Lib.PcbLib; Height: 0.40MM; Library Path: Y:\MIS_DATABASE\Library\ALTIUM_TOOL\SCHEMATICS_PARTS\MS_DISCRETE_Library.schlib; Mfr_name: PANASONIC-ECG; Mfr_part_number: ERJ-2RKF59R0X; Mistral Part No: 110009031010-R; Package: 0402; Part_type: RESISTORS\FIXED; Project: KHAN_HSST; RoHS: RoHS; Temperature: -55°C+155°C; Tolerance: 1%; Voltage: NA; Wattage: 1/10W; Weight: 0.8mg; Datasheet: Y:\MIS_DATABASE\DATASHEETS\RESISTORS\PAN-ERJSER_NOV17.PDF
R107 R110 R113 R117 R126 R131 = RESISTOR: RES 33E 1/10W 5% 0402; Chkd/date: VASANTHA/201216; Crtd /date: GEETHA/190406; Custom_Duty: 15%; Customs_HS_Code: 85332119; Distributor_name: DIGIKEY; Distributor_part_number: P33JCT-ND; Footprint Path: Y:\MIS_DATABASE\Library\ALTIUM_TOOL\PCB_FOOTPRINTS\Altium_Footprint_Lib.PcbLib; Height: 0.40MM; Library Path: Y:\MIS_DATABASE\Library\ALTIUM_TOOL\SCHEMATICS_PARTS\MS_DISCRETE_Library.schlib; Mfr_name: PANASONIC-ECG; Mfr_part_number: ERJ-2GEJ330X; Mistral Part No: 110009030699-R; Package: 0402; Part_type: RESISTORS\FIXED; Project: RED EYE; RoHS: RoHS; Temperature: -55°C+155°C; Tolerance: 5%; Voltage: NA; Wattage: 1/10W; Weight: 0.8mg; Datasheet: Y:\MIS_DATABASE\DATASHEETS\RESISTORS\PAN-ERJSER_NOV17.PDF
R152 = RESISTOR: RES 10K 1/16W 5% 0402; Assembly_Instruction: DNI; Chkd/date: VASANTHA/061216; Crtd /date: MAZHAR/230805; Custom_Duty: 15%; Customs_HS_Code: 85332119; Distributor_name: DIGIKEY; Distributor_part_number: 311-10KJRCT-ND; Footprint Path: Y:\MIS_DATABASE\Library\ALTIUM_TOOL\PCB_FOOTPRINTS\Altium_Footprint_Lib.PcbLib; Height: 0.40MM; Library Path: Y:\MIS_DATABASE\Library\ALTIUM_TOOL\SCHEMATICS_PARTS\MS_DISCRETE_Library.schlib; Mfr_name: YAGEO AMERICA; Mfr_part_number: RC0402JR-0710KL; Mistral Part No: 110011060021-R; Package: 0402; Part_type: RESISTORS\FIXED; Project: HSE; RoHS: RoHS; Temperature: -55°C+155°C; Tolerance: 5%; Voltage: NA; Wattage: 1/16W; Weight: 0.65mg; Datasheet: Y:\MIS_DATABASE\DATASHEETS\RESISTORS\RCXXXXL-SER_MAR18.PDF
U6-U9 U11 U15 = TCAN1042HGVD_SOIC8: IC AUTOMOTIVE FAULT PROTECTED CAN TRANSCEIVER WITH CAN FD SOIC8; Chkd/date: MANIRAJA/140818; Crtd /date: ALVY/140818; Custom_Duty: 15%; Customs_HS_Code: 85423100; Distributor_name: DIGIKEY; Distributor_part_number: 296-47722-ND; Footprint Path: Y:\MIS_DATABASE\Library\ALTIUM_TOOL\PCB_FOOTPRINTS\Altium_Footprint_Lib.PcbLib; Height: 1.75MM; Library Path: Y:\MIS_DATABASE\Library\ALTIUM_TOOL\SCHEMATICS_PARTS\MS_TELECOM_Library.schlib; Mfr_name: TEXAS INSTRUMENTS; Mfr_part_number: TCAN1042HGVDQ1; Mistral Part No: 143018080002-R; Package: SOIC8; Part_type: ICS\TELECOM\TRANSCEIVER; Project: TI_J7ES_GESI_BOARD; RoHS: RoHS; Temperature: -55°C+125°C; Tolerance: NA; Voltage: NA; Wattage: NA; Weight: 540mg; Datasheet: Y:\MIS_DATABASE\DATASHEETS\ICS\TELECOM\TCAN1042-Q1.PDF

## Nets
DGND: C9.2 C13.2 C15.2 C16.2 C17.2 C18.2 C19.2 C20.1 C21.1 C22.2 C23.2 C62.2 C63.1 C64.2 C65.2 C66.1 C67.2 C68.2 C69.2 C70.2 C71.1 C72.2 C73.2 C74.2 C75.1 C76.2 C77.2 C84.2 C86.1 C87.2 C88.2 C94.2 C100.1 C101.2 C102.2 C132.2 C133.2 C134.2 C135.2 C136.2 C137.2 C138.2 C139.2 J3.2 J6.2 J8.2 J10.2 J12.2 J14.2 J20.B10(GND) Q2.2(SOURCE) Q4.2(SOURCE) Q6.2(SOURCE) R151.1 R170.2 R171.2 R172.2 R173.2 R174.2 R175.2 R178.2 R181.2 R182.1 U2.3(GND) U3.49(EP) U6.2(GND) U7.2(GND) U8.2(GND) U9.2(GND) U11.2(GND) U15.2(GND) ; also on sheet 1 2 3 8 9 10 11 12 13 14 15 19 20 21 22 23 24
VCC_3V3: C65.1 C69.1 C73.1 C77.1 C88.1 C102.1 R21.2 R26.1 R49.1 R51.1 R152.2 U6.5(VIO) U7.5(VIO) U8.5(VIO) U9.5(VIO) U11.5(VIO) U15.5(VIO) ; also on sheet 1 2 3 8 9 10 11 12 13 14 15 19 20 22 23 24
VCC_5V0: C63.2 C64.1 C66.2 C67.1 C71.2 C72.1 C75.2 C76.1 C86.2 C87.1 C100.2 C101.1 U6.3(VCC) U7.3(VCC) U8.3(VCC) U9.3(VCC) U11.3(VCC) U15.3(VCC) ; also on sheet 8 20 21 23 24
VDD_1V0: C15.1 C19.1 C23.1 C133.1 C134.1 C136.1 C137.1 U3.6(VDDA1P0) U3.24(VDD1P0) U3.31(VDD1P0) U3.42(VDD1P0) ; also on sheet 13 14 15 23
VDD_2V5: C13.1 C17.1 C135.1 C139.1 U3.3(VDDA2P5) U3.9(VDDA2P5) ; also on sheet 13 14 15 23
VDD_IO_PHY: C9.1 C16.1 C18.1 C22.1 C132.1 C138.1 R10.1 R11.1 R12.1 R13.1 R14.1 R15.1 R179.1 R180.1 U2.5(VCC) U3.19(VDDIO) U3.30(VDDIO) U3.41(VDDIO) ; also on sheet 12 13 14 15
CAN1_H: J14.1 R129.1 U15.7(CANH)
CAN1_L: J14.3 R130.2 U15.6(CANL)
CAN1_RXD: R131.2 U15.4(RXD)
CAN1_T: C94.1 R129.2 R130.1
CAN2_H: J12.1 R118.1 U11.7(CANH)
CAN2_L: J12.3 R121.2 U11.6(CANL)
CAN2_RXD: R126.2 U11.4(RXD)
CAN2_T: C84.1 R118.2 R121.1
CAN3_H: J10.1 R114.1 U9.7(CANH)
CAN3_L: J10.3 R115.2 U9.6(CANL)
CAN3_RXD: R117.2 U9.4(RXD)
CAN3_T: C74.1 R114.2 R115.1
CAN4_H: J8.1 R111.1 U8.7(CANH)
CAN4_L: J8.3 R112.2 U8.6(CANL)
CAN4_RXD: R113.2 U8.4(RXD)
CAN4_T: C70.1 R111.2 R112.1
CAN5_H: J6.1 R108.1 U7.7(CANH)
CAN5_L: J6.3 R109.2 U7.6(CANL)
CAN5_RXD: R110.2 U7.4(RXD)
CAN5_T: C68.1 R108.2 R109.1
CAN6_H: J3.1 R105.1 U6.7(CANH)
CAN6_L: J3.3 R106.2 U6.6(CANL)
CAN6_RXD: R107.2 U6.4(RXD)
CAN6_T: C62.1 R105.2 R106.1
CAN_STB: R151.2 R152.1 U6.8(STB) U7.8(STB) U8.8(STB) U9.8(STB) U11.8(STB) U15.8(STB) ; also on sheet 8
ETH_EARTH: J20.SH3 J20.SH4 ; also on sheet 13 14 15 22
GPIO_PRG1_RGMII2_RST: R20.2 R21.1 U2.2(B)
GPIO_PRG1_RGMII_RST: R20.1 ; also on sheet 8 15
MCAN4_RX: J15.2 R131.1 ; also on sheet 9
MCAN4_TX: J15.1 U15.1(TXD) ; also on sheet 9
MCAN5_RX: J13.2 R126.1 ; also on sheet 9
MCAN5_TX: J13.1 U11.1(TXD) ; also on sheet 9
MCAN6_RX: J11.2 R117.1 ; also on sheet 9
MCAN6_TX: J11.1 U9.1(TXD) ; also on sheet 9
MCAN7_RX: J9.2 R113.1 ; also on sheet 9
MCAN7_TX: J9.1 U8.1(TXD) ; also on sheet 9
MCAN9_RX: J7.2 R110.1 ; also on sheet 8
MCAN9_TX: J7.1 U7.1(TXD) ; also on sheet 8
MCAN11_RX: J4.2 R107.1 ; also on sheet 8
MCAN11_TX: J4.1 U6.1(TXD) ; also on sheet 8
PRG1_MDC: U3.16(MDC) ; also on sheet 12 15
PRG1_MDIO: U3.17(MDIO) ; also on sheet 12 15
PRG1_RGMII2_100Mbps: J20.B13 Q4.3(DRAIN) R49.2
PRG1_RGMII2_1000Mbps: J20.B14 Q6.3(DRAIN) R51.2
PRG1_RGMII2_ACT_LED: J20.B11 Q2.3(DRAIN)
PRG1_RGMII2_CLK_OUT: TP11.1(TP) U3.18(CLK_OUT)
PRG1_RGMII2_D0_N: J20.B2(TD1-_2) U3.2(TD_M_A)
PRG1_RGMII2_D0_P: J20.B1(TD1+_2) U3.1(TD_P_A)
PRG1_RGMII2_D1_N: J20.B4(TD2-_2) U3.5(TD_M_B)
PRG1_RGMII2_D1_P: J20.B3(TD2+_2) U3.4(TD_P_B)
PRG1_RGMII2_D2_N: J20.B6(TD3-_2) U3.8(TD_M_C)
PRG1_RGMII2_D2_P: J20.B5(TD3+_2) U3.7(TD_P_C)
PRG1_RGMII2_D3_N: J20.B8(TD4-_2) U3.11(TD_M_D)
PRG1_RGMII2_D3_P: J20.B7(TD4+_2) U3.10(TD_P_D)
PRG1_RGMII2_GPIO0_100: Q4.1(GATE) R14.2 R171.1 U3.39(GPIO_0)
PRG1_RGMII2_GPIO1: R13.2 R172.1 U3.40(GPIO_1)
PRG1_RGMII2_LED0: R10.2 R175.1 U3.47(LED0)
PRG1_RGMII2_LED1_1000: Q6.1(GATE) R11.2 R174.1 U3.46(LED1)
PRG1_RGMII2_LED2_ACT: Q2.1(GATE) R12.2 R173.1 U3.45(LED2)
PRG1_RGMII2_RBIAS: R182.2 U3.12(RBIAS)
PRG1_RGMII2_RD0: R24.1 TP42.1(TP) ; also on sheet 8
PRG1_RGMII2_RD0_R: R24.2 R180.2 R181.1 U3.33(RX_D0/SGMII_COP)
PRG1_RGMII2_RD1: R23.1 TP43.1(TP) ; also on sheet 8
PRG1_RGMII2_RD1_R: R23.2 U3.34(RX_D1/SGMII_CON)
PRG1_RGMII2_RD2: R22.1 TP44.1(TP) ; also on sheet 8
PRG1_RGMII2_RD2_R: R22.2 R178.1 R179.2 U3.35(RX_D2/SGMII_SOP)
PRG1_RGMII2_RD3: R19.1 TP45.1(TP) ; also on sheet 8
PRG1_RGMII2_RD3_R: R19.2 U3.36(RX_D3/SGMII_SON)
PRG1_RGMII2_REF_CLK: R32.1 ; also on sheet 9
PRG1_RGMII2_RESET#: U2.4(Y) U3.43(RESET_N)
PRG1_RGMII2_RX_CTL: R16.1 TP46.1(TP) ; also on sheet 8
PRG1_RGMII2_RX_CTL_R: R15.2 R16.2 R170.1 U3.38(RX_CTRL)
PRG1_RGMII2_RXC: R25.1 TP47.1(TP) ; also on sheet 8
PRG1_RGMII2_RXC_R: R25.2 U3.32(RX_CLK)
PRG1_RGMII2_TD0: R29.1 TP36.1(TP) ; also on sheet 8
PRG1_RGMII2_TD0_R: R29.2 U3.28(TX_D0/SGMII_SIN)
PRG1_RGMII2_TD1: R30.1 TP37.1(TP) ; also on sheet 8
PRG1_RGMII2_TD1_R: R30.2 U3.27(TX_D1/SGMII_SIP)
PRG1_RGMII2_TD2: R31.1 TP38.1(TP) ; also on sheet 8
PRG1_RGMII2_TD2_R: R31.2 U3.26(TX_D2)
PRG1_RGMII2_TD3: R35.1 TP39.1(TP) ; also on sheet 8
PRG1_RGMII2_TD3_R: R35.2 U3.25(TX_D3)
PRG1_RGMII2_TX_CTL: R17.1 TP40.1(TP) ; also on sheet 8
PRG1_RGMII2_TX_CTL_R: R17.2 U3.37(TX_CTRL)
PRG1_RGMII2_TXC: R28.1 TP41.1(TP) ; also on sheet 8
PRG1_RGMII2_TXC_R: R28.2 U3.29(GTX_CLK)
PRG1_RGMII2_XIN: R32.2 R34.2 U3.15(X_I)
PRG1_RGMII2_XOUT: R33.2 U3.14(X_O)
PRG1_RGMII_INT#: U3.44(INT/PWDN) ; also on sheet 8 15
SOC_PORZ_OUT: U2.1(A) ; also on sheet 8 13 14 15 22
N23048841: J20.B12 R26.2
N23049007: C21.2 R34.1 Y1.2
N23049009: C20.2 R33.1 Y1.1
N23111061: TP7.1(TP) U3.13(VDDA1P8) U3.48(VDDA1P8)

Not connected (* = marked no-connect by the designer): J20 B9(VCC2)*; U3 20(JTAG_CLK)* 21(JTAG_TDO)* 22(JTAG_TMS)* 23(JTAG_TDI)*

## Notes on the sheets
sheet 16
- PRG1 GB_ETHERNET RGMII 2
- Silk Screen for J20 TOP :
  "PRG1_RGMII2"
- PCB Note:  Route signals as 100-ohm differential
- RJ45
- RESET LOGIC
- RJ45-LED
- FUNCTION
- YELLOW
- ACTIVITY
- ORANGE
- 1000Mbps Speed
- GREEN
- 100Mbps Speed
- SPEED AND ACTIVITY LED DRIVERS
- PHY ADD = 01111
- Auto_neg = Enabled
  ANEGsel 10/100/1000
- RGMII Clock Skew TX = 0ns
  RGMII Clock Skew RX = 2ns
sheet 17
- CAN TRANSCEIVERS - 01
- Silkscreen for
  J15:   "MCAN4"
- CAN1_TXD
- Silkscreen for
  J14:   "CAN1"
- Silkscreen for
  J13:   "MCAN5"
- CAN2_TXD
- Silkscreen for
  J12:   "CAN2"
- Silkscreen for
  J11:   "MCAN6"
- CAN3_TXD
- Silkscreen for
  J10:   "CAN3"
sheet 18
- CAN TRANSCEIVERS - 02
- Silkscreen for
  J9:   "MCAN7"
- CAN4_TXD
- Silkscreen for
  J8:   "CAN4"
- Silkscreen for
  J7:   "MCAN9"
- CAN5_TXD
- Silkscreen for
  J6:   "CAN5"
- Silkscreen for
  J4:   "MCAN11"
- CAN6_TXD
- Silkscreen for
  J3:   "CAN6"
